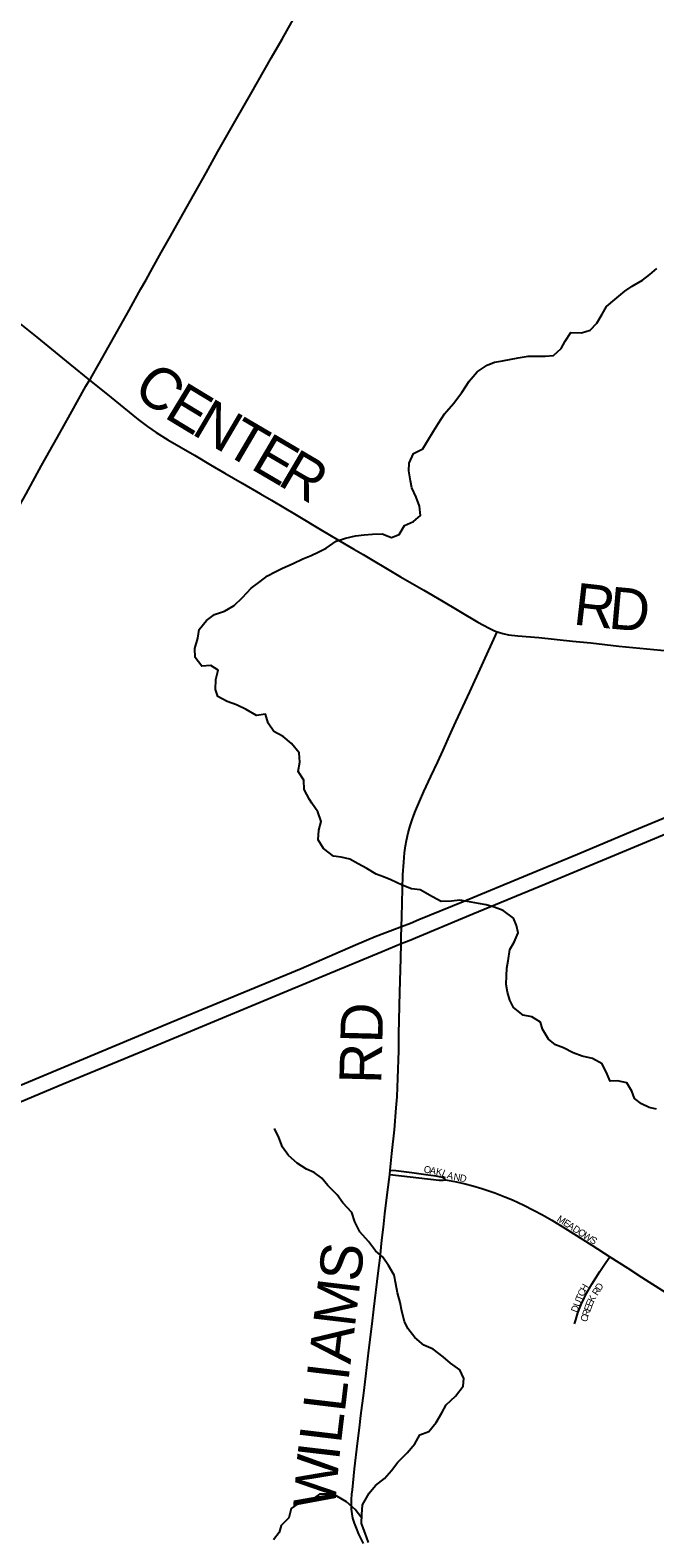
# Model space of a CAD drawing. Extents: x 1442749 to 1756758, y 235267 to 677782.
# Drawn here: x 1568709 to 1573169, y 544190 to 554957 of the extents above; entities that cross this region are included whole.
import ezdxf

# ---------------------------------------------------------------- set-up
doc = ezdxf.new("R2010")
doc.units = 0
for name, color, linetype in [('GM_X_County_Road', 7, 'Continuous'), ('GM_X_County_Road_Text', 7, 'Continuous'), ('GM_X_Interstate_Route', 7, 'Continuous'), ('GM_X_Minor_River', 7, 'Continuous'), ('GM_X_Township_Road', 7, 'Continuous'), ('GM_X_Township_Subdivision', 7, 'Continuous'), ('GM_X_Township_Subdivision_Text', 7, 'Continuous')]:
    doc.layers.add(name, color=color, linetype=linetype)

msp = doc.modelspace()

# ---------------------------------------------------------------- linework, layer by layer
at = {"layer": 'GM_X_County_Road'}
for points in [[(1568578, 552908), (1568758, 552765), (1568993, 552571), (1569134, 552457)], [(1569134, 552457), (1569249, 552365), (1569481, 552177), (1569546, 552127), (1569609, 552084), (1569693, 552032), (1569883, 551922), (1569998, 551854), (1570100, 551793), (1570224, 551721), (1570355, 551645), (1570432, 551601), (1570609, 551495), (1570795, 551385), (1570964, 551284), (1571021, 551251), (1571086, 551212), (1571159, 551169), (1571247, 551118), (1571354, 551054), (1571521, 550957), (1571645, 550883), (1571906, 550730), (1571987, 550686), (1572025, 550667), (1572044, 550660)], [(1571279, 546817), (1571292, 546934), (1571310, 547104), (1571323, 547261), (1571329, 547340), (1571334, 547474), (1571341, 547668), (1571342, 547789), (1571349, 548087), (1571355, 548327), (1571357, 548434), (1571358, 548478), (1571360, 548557), (1571362, 548625), (1571367, 548825), (1571371, 548926), (1571376, 549015), (1571383, 549083), (1571390, 549131), (1571397, 549170), (1571409, 549224), (1571423, 549275), (1571437, 549318), (1571449, 549351), (1571461, 549382), (1571474, 549416), (1571488, 549449), (1571521, 549521), (1571571, 549627), (1571619, 549732), (1571657, 549815), (1571712, 549938), (1571749, 550018), (1571849, 550232), (1572031, 550634), (1572044, 550660)], [(1572044, 550660), (1572053, 550657), (1572085, 550648), (1572124, 550640), (1572190, 550633), (1572340, 550619), (1572581, 550594), (1572712, 550581), (1572911, 550559), (1573263, 550524), (1573499, 550500), (1573701, 550482), (1573848, 550469), (1573943, 550456), (1574023, 550442), (1574090, 550427), (1574156, 550409), (1574212, 550389), (1574260, 550369), (1574314, 550340), (1574373, 550304), (1574429, 550265), (1574441, 550256)], [(1571089, 544150), (1571056, 544217), (1571038, 544259), (1571024, 544296), (1571014, 544330), (1571008, 544362), (1571004, 544394), (1571003, 544430), (1571004, 544465), (1571006, 544501), (1571010, 544534), (1571025, 544684), (1571046, 544863), (1571060, 544977), (1571071, 545065), (1571091, 545224), (1571107, 545344), (1571128, 545530), (1571151, 545719), (1571164, 545823), (1571193, 546081), (1571207, 546191), (1571221, 546315), (1571232, 546410), (1571242, 546504), (1571261, 546660), (1571276, 546786)], [(1571276, 546786), (1571279, 546817)]]:
    msp.add_lwpolyline(points, dxfattribs=at)
at = {"layer": 'GM_X_Interstate_Route'}
for points in [[(1568252, 547142), (1568944, 547433), (1569527, 547672), (1570820, 548211), (1571223, 548378), (1571357, 548434), (1571414, 548457), (1571869, 548646), (1572384, 548859), (1573977, 549523), (1574847, 549911), (1575112, 550030), (1575702, 550286), (1576273, 550536), (1576583, 550673), (1576675, 550714), (1577606, 551123), (1578020, 551308), (1578737, 551624), (1578788, 551646), (1579322, 551884), (1579929, 552149), (1580388, 552353), (1581057, 552648)], [(1568144, 547217), (1569716, 547872), (1570643, 548257), (1571031, 548425), (1571173, 548485), (1571329, 548545), (1571360, 548557), (1571424, 548580), (1571485, 548605), (1571801, 548734), (1572261, 548926), (1572616, 549073), (1573012, 549239), (1573782, 549558)]]:
    msp.add_lwpolyline(points, dxfattribs=at)
at = {"layer": 'GM_X_Minor_River'}
for points in [[(1570720, 549436), (1570703, 549463), (1570666, 549534), (1570663, 549601), (1570622, 549664), (1570634, 549729), (1570629, 549796), (1570576, 549863), (1570515, 549912), (1570448, 549948), (1570409, 550007), (1570390, 550073), (1570326, 550062), (1570252, 550106), (1570183, 550139), (1570115, 550163), (1570050, 550198), (1570033, 550249), (1570034, 550319), (1570051, 550387), (1570000, 550420), (1569934, 550415), (1569887, 550476), (1569884, 550542), (1569906, 550614), (1569917, 550678), (1569968, 550741), (1570025, 550784), (1570096, 550809), (1570165, 550848), (1570226, 550906), (1570288, 550973), (1570351, 551020), (1570404, 551061), (1570458, 551088), (1570511, 551115), (1570588, 551148), (1570657, 551181), (1570715, 551205), (1570770, 551232), (1570822, 551257), (1570894, 551308), (1570960, 551329), (1571033, 551346), (1571093, 551352), (1571153, 551359), (1571223, 551360), (1571289, 551334), (1571344, 551355), (1571381, 551419), (1571446, 551448), (1571497, 551491), (1571488, 551557), (1571465, 551622), (1571434, 551688), (1571425, 551739), (1571413, 551811), (1571414, 551865), (1571447, 551933), (1571512, 551968), (1571549, 552027), (1571589, 552094), (1571624, 552150), (1571667, 552217), (1571731, 552292), (1571791, 552369), (1571843, 552450), (1571900, 552517), (1571971, 552564), (1572024, 552587), (1572082, 552596), (1572193, 552616), (1572265, 552628), (1572337, 552629), (1572387, 552628), (1572446, 552633), (1572501, 552684), (1572530, 552735), (1572569, 552797), (1572645, 552795), (1572708, 552814), (1572755, 552865), (1572792, 552930), (1572823, 552984), (1572884, 553033), (1572956, 553094), (1573007, 553129), (1573080, 553171), (1573133, 553212), (1573184, 553255)], [(1571493, 548817), (1571431, 548824), (1571366, 548851), (1571285, 548889), (1571231, 548910), (1571180, 548929), (1571112, 548971), (1571051, 549004), (1570992, 549037), (1570930, 549052), (1570876, 549059), (1570803, 549113), (1570765, 549176), (1570770, 549244), (1570787, 549307), (1570763, 549374), (1570720, 549436)], [(1573181, 547251), (1573128, 547264), (1573074, 547289), (1573023, 547328), (1573004, 547381), (1572969, 547440), (1572902, 547453), (1572850, 547452), (1572829, 547502), (1572792, 547575), (1572723, 547613), (1572651, 547630), (1572586, 547655), (1572516, 547689), (1572461, 547712), (1572410, 547751), (1572367, 547822), (1572352, 547872), (1572291, 547912), (1572229, 547923), (1572160, 547978), (1572133, 548029), (1572118, 548087), (1572108, 548142), (1572109, 548204), (1572112, 548258), (1572121, 548312), (1572133, 548391), (1572164, 548445), (1572193, 548512), (1572182, 548563), (1572159, 548615), (1572086, 548671), (1572023, 548694), (1571965, 548711), (1571909, 548720), (1571832, 548734), (1571776, 548745), (1571718, 548736), (1571644, 548734), (1571582, 548767), (1571493, 548817)], [(1570738, 546799), (1570682, 546822), (1570615, 546867), (1570554, 546920), (1570512, 546981), (1570485, 547050), (1570454, 547113)], [(1571124, 544157), (1571101, 544224), (1571076, 544292), (1571078, 544356), (1571081, 544426), (1571129, 544509), (1571174, 544565), (1571239, 544615), (1571288, 544671), (1571335, 544730), (1571401, 544798), (1571456, 544861), (1571491, 544925), (1571556, 544950), (1571607, 545015), (1571649, 545084), (1571680, 545139), (1571747, 545202), (1571801, 545273), (1571806, 545327), (1571777, 545390), (1571710, 545437), (1571657, 545482), (1571586, 545538), (1571519, 545567), (1571456, 545621), (1571405, 545686), (1571382, 545736), (1571362, 545809), (1571351, 545871), (1571332, 545940), (1571320, 546004), (1571309, 546066), (1571268, 546135), (1571227, 546194), (1571174, 546239), (1571126, 546306), (1571063, 546376), (1571027, 546446), (1571006, 546513), (1570941, 546582), (1570901, 546639), (1570834, 546707), (1570791, 546758), (1570738, 546799)], [(1571077, 544330), (1571029, 544393), (1570968, 544447), (1570898, 544488), (1570847, 544501), (1570775, 544502), (1570714, 544458), (1570636, 544445), (1570573, 544400), (1570557, 544332), (1570502, 544279), (1570487, 544228), (1570446, 544176)]]:
    msp.add_lwpolyline(points, dxfattribs=at)
at = {"layer": 'GM_X_Township_Road'}
for points in [[(1569134, 552457), (1569143, 552471), (1569202, 552577), (1569288, 552728), (1569416, 552957), (1569500, 553109), (1569537, 553174), (1569583, 553258), (1569645, 553370), (1569711, 553487), (1569800, 553644), (1569965, 553939), (1570049, 554091), (1570183, 554324), (1570283, 554498), (1570433, 554763), (1570508, 554894), (1570663, 555168)], [(1567329, 549216), (1567376, 549299), (1567426, 549388), (1567625, 549750), (1567684, 549859), (1567933, 550303), (1568018, 550454), (1568145, 550684), (1568233, 550841), (1568308, 550976), (1568378, 551098), (1568424, 551182), (1568551, 551411), (1568637, 551570), (1568680, 551647), (1568791, 551848), (1568905, 552051), (1568995, 552212), (1569108, 552415), (1569134, 552457)]]:
    msp.add_lwpolyline(points, dxfattribs=at)
at = {"layer": 'GM_X_Township_Subdivision'}
for points in [[(1571276, 546786), (1571629, 546745), (1571642, 546744), (1571659, 546745), (1571674, 546748)], [(1571279, 546817), (1571320, 546813), (1571434, 546799), (1571534, 546786), (1571605, 546775), (1571653, 546765), (1571666, 546758), (1571674, 546748)], [(1571674, 546748), (1571752, 546733), (1571816, 546719), (1571870, 546705), (1571933, 546685), (1572026, 546653), (1572097, 546626), (1572152, 546604), (1572233, 546566), (1572303, 546531), (1572367, 546497), (1572433, 546460), (1572527, 546401), (1572719, 546280), (1572847, 546197)], [(1572596, 545718), (1572604, 545746), (1572620, 545796), (1572644, 545856), (1572664, 545901), (1572682, 545936), (1572719, 546001), (1572777, 546092), (1572820, 546157), (1572847, 546197)], [(1572847, 546197), (1572848, 546196), (1572976, 546115), (1573075, 546051), (1573249, 545939), (1573399, 545844), (1573486, 545792), (1573687, 545662)]]:
    msp.add_lwpolyline(points, dxfattribs=at)

# ---------------------------------------------------------------- texts
at = {"layer": 'GM_X_County_Road_Text'}
for s, rotation, p in [('C', 321.7108, (1569431, 552372)), ('E', 328.7511, (1569657, 552196)), ('N', 329.5236, (1569853, 552077)), ('T', 329.5437, (1570080, 551943)), ('E', 329.5386, (1570274, 551830)), ('R', 329.5469, (1570467, 551716)), ('R', 353.523, (1572580, 550714)), ('D', 354.8882, (1572832, 550685)), ('RD', 88.544, (1571216, 547430)), ('S', 83.222, (1571065, 546012)), ('M', 83.2223, (1571027, 545688)), ('A', 83.2257, (1570996, 545426)), ('I', 83.2197, (1570981, 545304)), ('L', 83.2234, (1570955, 545081)), ('L', 83.2194, (1570928, 544858)), ('I', 83.299, (1570914, 544736)), ('W', 85.3356, (1570886, 544392))]:
    msp.add_text(s, height=300, rotation=rotation, dxfattribs=at).set_placement(p)
at = {"layer": 'GM_X_Township_Subdivision_Text'}
for s, rotation, p in [('O', 349.183, (1571516, 546800)), ('A', 349.183, (1571559, 546792)), ('K', 349.183, (1571603, 546783)), ('L', 336.6256, (1571643, 546776)), ('A', 343.268, (1571681, 546760)), ('N', 349.8755, (1571729, 546746)), ('D', 349.2709, (1571773, 546738)), ('M', 327.2396, (1572465, 546455)), ('E', 327.204, (1572510, 546427)), ('A', 327.2607, (1572540, 546408)), ('D', 327.2497, (1572577, 546384)), ('O', 327.207, (1572614, 546360)), ('W', 327.2506, (1572651, 546336)), ('S', 328.3772, (1572700, 546305)), ('H', 59.7278, (1572675, 545944)), ('D', 56.9193, (1572780, 545950)), ('U', 68.4157, (1572631, 545836)), ('T', 68.4015, (1572647, 545877)), ('C', 66.0757, (1572660, 545909)), ('E', 67.8763, (1572719, 545836)), ('K', 62.4476, (1572732, 545867)), ('R', 57.2429, (1572759, 545916)), ('D', 68.4157, (1572614, 545795)), ('C', 71.542, (1572683, 545728)), ('R', 71.4114, (1572695, 545766)), ('E', 70.4804, (1572708, 545803))]:
    msp.add_text(s, height=50, rotation=rotation, dxfattribs=at).set_placement(p)

doc.saveas('drawing.dxf')
